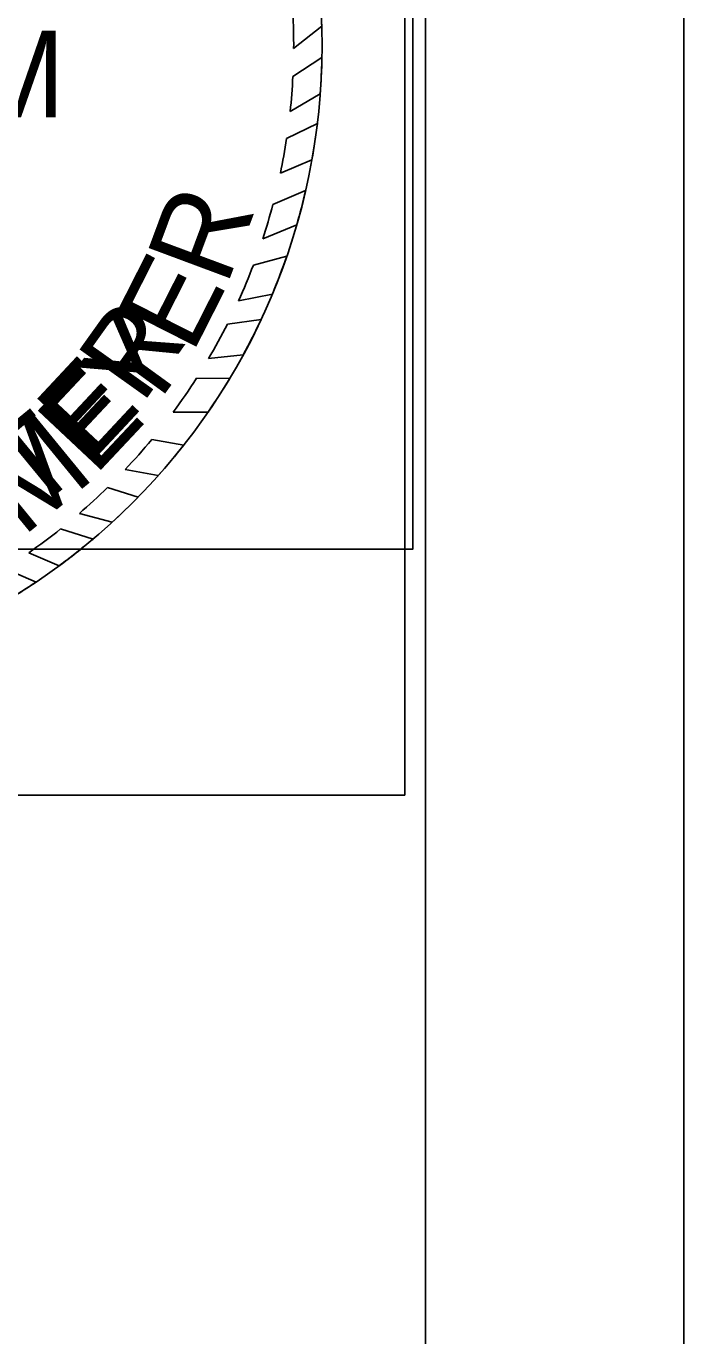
# Model space of a CAD drawing. Extents: x -0.29 to 1.42, y 0 to 0.92.
# Drawn here: x 1.3636 to 1.4167, y 0.689 to 0.7945 of the extents above; entities that cross this region are included whole.
import ezdxf

# ---------------------------------------------------------------- set-up
doc = ezdxf.new("R2010")
doc.units = 0
for name, color, linetype in [('DSN_DRFT_Guideline-No-Plot', 7, 'Continuous'), ('SHET_Border-Lines', 7, 'Continuous'), ('SHET_Stamp-Seal', 7, 'Continuous'), ('STAMP_PE_BACKGROUND', 7, 'Continuous'), ('STAMP_PE_FOSTER', 7, 'Continuous'), ('STAMP_PE_SEAL-INFO', 7, 'Continuous'), ('STAMP_PE_TAEGTMEYER', 7, 'Continuous'), ('STAMP_PRELIMINARY', 7, 'Continuous')]:
    doc.layers.add(name, color=color, linetype=linetype)

msp = doc.modelspace()

# ---------------------------------------------------------------- linework, layer by layer
at = {"layer": 'DSN_DRFT_Guideline-No-Plot'}
msp.add_lwpolyline([(0, 0), (1.416666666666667, 0), (1.416666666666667, 0.9166666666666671), (0, 0.9166666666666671)], close=True, dxfattribs=at)
at = {"layer": 'SHET_Border-Lines'}
msp.add_lwpolyline([(0.02083333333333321, 0.02083333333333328), (1.3958333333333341, 0.02083333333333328), (1.3958333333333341, 0.8958333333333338), (0.02083333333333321, 0.8958333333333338)], close=True, dxfattribs=at)
at = {"layer": 'SHET_Stamp-Seal'}
msp.add_lwpolyline([(1.2948333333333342, 0.7523810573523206), (1.3948333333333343, 0.7523810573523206), (1.3948333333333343, 0.8523810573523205), (1.2948333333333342, 0.8523810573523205)], close=True, dxfattribs=at)
at = {"layer": 'STAMP_PE_BACKGROUND'}
msp.add_lwpolyline([(1.3941666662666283, 0.8517143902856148), (1.2749999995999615, 0.8517143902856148), (1.2749999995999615, 0.7325477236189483), (1.3941666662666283, 0.7325477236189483)], close=True, dxfattribs=at)
msp.add_lwpolyline([(1.3941666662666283, 0.8517143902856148), (1.2749999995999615, 0.8517143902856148), (1.2749999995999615, 0.7325477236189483), (1.3941666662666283, 0.7325477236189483)], close=True, dxfattribs=at)
at = {"layer": 'STAMP_PE_SEAL-INFO'}
for p, q in [((1.3852134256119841, 0.7927322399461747), (1.3874764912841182, 0.7945290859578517)), ((1.3852134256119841, 0.7927322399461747), (1.3874764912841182, 0.7945290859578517)), ((1.3851513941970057, 0.7904687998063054), (1.3874913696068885, 0.7920162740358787)), ((1.3851513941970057, 0.7904687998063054), (1.3874913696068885, 0.7920162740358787)), ((1.3849286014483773, 0.7876409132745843), (1.3873544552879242, 0.7890734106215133)), ((1.3849286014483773, 0.7876409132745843), (1.3873544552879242, 0.7890734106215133)), ((1.3846467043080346, 0.78546942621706), (1.3871215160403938, 0.7866968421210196)), ((1.3846467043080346, 0.78546942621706), (1.3871215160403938, 0.7866968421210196)), ((1.3841397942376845, 0.7826771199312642), (1.3866817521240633, 0.7837684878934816)), ((1.3841397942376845, 0.7826771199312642), (1.3866817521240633, 0.7837684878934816)), ((1.383537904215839, 0.7801535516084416), (1.38617225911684, 0.7812792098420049)), ((1.383537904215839, 0.7801535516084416), (1.38617225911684, 0.7812792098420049)), ((1.382716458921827, 0.7773919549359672), (1.3854553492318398, 0.7785143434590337)), ((1.382716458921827, 0.7773919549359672), (1.3854553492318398, 0.7785143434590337)), ((1.3819640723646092, 0.7752694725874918), (1.3846604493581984, 0.7760019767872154)), ((1.3819640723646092, 0.7752694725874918), (1.3846604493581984, 0.7760019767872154)), ((1.380767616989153, 0.772395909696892), (1.383494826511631, 0.7729353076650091)), ((1.380767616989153, 0.772395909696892), (1.383494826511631, 0.7729353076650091)), ((1.3798679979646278, 0.7705177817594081), (1.3825944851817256, 0.7708979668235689)), ((1.3798679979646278, 0.7705177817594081), (1.3825944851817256, 0.7708979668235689)), ((1.378347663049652, 0.7677314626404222), (1.3811465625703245, 0.7680354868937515)), ((1.378347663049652, 0.7677314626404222), (1.3811465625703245, 0.7680354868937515)), ((1.377387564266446, 0.7661648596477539), (1.3800548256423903, 0.7661295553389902)), ((1.377387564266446, 0.7661648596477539), (1.3800548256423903, 0.7661295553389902)), ((1.3754905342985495, 0.7634033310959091), (1.3783092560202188, 0.7634195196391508)), ((1.3754905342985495, 0.7634033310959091), (1.3783092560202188, 0.7634195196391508)), ((1.3737701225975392, 0.7612030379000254), (1.376349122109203, 0.7607586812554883)), ((1.3737701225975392, 0.7612030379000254), (1.376349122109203, 0.7607586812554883)), ((1.3716298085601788, 0.7587828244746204), (1.374294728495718, 0.7583064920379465)), ((1.3716298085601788, 0.7587828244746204), (1.374294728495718, 0.7583064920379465)), ((1.3702058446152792, 0.7573345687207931), (1.3726690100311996, 0.7565647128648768)), ((1.3702058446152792, 0.7573345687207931), (1.3726690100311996, 0.7565647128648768)), ((1.367938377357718, 0.7552535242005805), (1.3705713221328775, 0.7545349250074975)), ((1.367938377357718, 0.7552535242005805), (1.3705713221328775, 0.7545349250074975)), ((1.3664259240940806, 0.7540003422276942), (1.3690398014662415, 0.7531880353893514)), ((1.3664259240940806, 0.7540003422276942), (1.3690398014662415, 0.7531880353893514)), ((1.3638530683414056, 0.7520847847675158), (1.3663034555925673, 0.7510277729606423)), ((1.3638530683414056, 0.7520847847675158), (1.3663034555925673, 0.7510277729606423)), ((1.3619321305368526, 0.7508134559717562), (1.364443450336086, 0.7497195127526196)), ((1.3619321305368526, 0.7508134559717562), (1.364443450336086, 0.7497195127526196))]:
    msp.add_line(p, q, dxfattribs=at)
for radius, start, end in [(0.05208333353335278, 1.7215475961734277, 4.7268136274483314), (0.05208333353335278, 1.7215475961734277, 4.7268136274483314), (0.04979730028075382, 359.7328912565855, 3.0639197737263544), (0.04979730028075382, 359.7328912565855, 3.0639197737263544), (0.05208333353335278, 355.71562332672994, 358.956939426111), (0.05208333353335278, 355.71562332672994, 358.956939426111), (0.04979730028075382, 353.86318650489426, 357.12741991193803), (0.04979730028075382, 353.86318650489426, 357.12741991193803), (0.05208333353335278, 349.83046937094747, 353.08845194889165), (0.05208333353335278, 349.83046937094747, 353.08845194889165), (0.04979730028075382, 348.07782395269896, 351.34354893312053), (0.04979730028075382, 348.07782395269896, 351.34354893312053), (0.05208333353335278, 343.8924710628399, 347.03501976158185), (0.05208333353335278, 343.8924710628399, 347.03501976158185), (0.04979730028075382, 341.7769864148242, 345.0924752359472), (0.04979730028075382, 341.7769864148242, 345.0924752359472), (0.05208333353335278, 337.3836727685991, 340.99332282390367), (0.05208333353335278, 337.3836727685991, 340.99332282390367), (0.04979730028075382, 335.60379596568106, 339.1857838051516), (0.04979730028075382, 335.60379596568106, 339.1857838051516), (0.05208333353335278, 331.4037138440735, 334.933154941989), (0.05208333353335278, 331.4037138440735, 334.933154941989), (0.04979730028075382, 329.55488416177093, 333.20757358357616), (0.04979730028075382, 329.55488416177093, 333.20757358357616), (0.04979730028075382, 323.58513069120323, 327.44068976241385), (0.04979730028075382, 323.58513069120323, 327.44068976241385), (0.05208333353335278, 325.4405170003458, 328.9872482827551), (0.05208333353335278, 325.4405170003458, 328.9872482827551), (0.04979730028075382, 316.6530849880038, 320.3710862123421), (0.04979730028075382, 316.6530849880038, 320.3710862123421), (0.05208333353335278, 318.2845512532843, 321.8042854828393), (0.05208333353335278, 318.2845512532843, 321.8042854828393), (0.04979730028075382, 310.7743619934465, 314.31605044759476), (0.04979730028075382, 310.7743619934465, 314.31605044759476), (0.05208333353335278, 312.45177291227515, 315.66328088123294), (0.05208333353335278, 312.45177291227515, 315.66328088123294), (0.04979730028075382, 304.8229923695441, 308.51427595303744), (0.04979730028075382, 304.8229923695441, 308.51427595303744), (0.05208333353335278, 306.37206251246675, 310.20798964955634), (0.05208333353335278, 306.37206251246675, 310.20798964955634), (0.05208333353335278, 300.6210136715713, 303.87026284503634), (0.05208333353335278, 300.6210136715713, 303.87026284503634)]:
    msp.add_arc((1.3354166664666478, 0.7929643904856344), radius, start, end, dxfattribs=at)
at = {"layer": 'STAMP_PRELIMINARY'}
msp.add_circle((1.3354166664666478, 0.7929643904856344), 0.05208333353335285, dxfattribs=at)
msp.add_circle((1.3354166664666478, 0.7929643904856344), 0.05208333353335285, dxfattribs=at)

# ---------------------------------------------------------------- texts
at = {"layer": 'STAMP_PE_FOSTER'}
for s, height, rotation, p in [('R', 0.006704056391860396, 54.50309997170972, (1.372983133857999, 0.763975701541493)), ('R', 0.006704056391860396, 54.50309997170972, (1.372983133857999, 0.763975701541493)), ('E', 0.006704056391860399, 46.96130660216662, (1.3689405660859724, 0.7593892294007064)), ('E', 0.006704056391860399, 46.96130660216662, (1.3689405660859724, 0.7593892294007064)), ('T', 0.006704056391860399, 39.41937898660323, (1.3641451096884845, 0.7551985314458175)), ('T', 0.006704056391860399, 39.41937898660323, (1.3641451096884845, 0.7551985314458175))]:
    msp.add_text(s, height=height, rotation=rotation, dxfattribs=at).set_placement(p)
at = {"layer": 'STAMP_PE_TAEGTMEYER'}
for s, height, rotation, p in [('R', 0.006983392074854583, 69.57000985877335, (1.379803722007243, 0.7734919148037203)), ('R', 0.006983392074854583, 69.57000985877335, (1.379803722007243, 0.7734919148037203)), ('E', 0.00698339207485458, 63.09839547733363, (1.3770182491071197, 0.7680080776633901)), ('E', 0.00698339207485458, 63.09839547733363, (1.3770182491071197, 0.7680080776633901)), ('Y', 0.006983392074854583, 53.99864225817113, (1.3732806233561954, 0.7627534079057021)), ('Y', 0.006983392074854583, 53.99864225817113, (1.3732806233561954, 0.7627534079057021)), ('E', 0.006983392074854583, 46.80937910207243, (1.3691516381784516, 0.758199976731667)), ('E', 0.006983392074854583, 46.80937910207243, (1.3691516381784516, 0.758199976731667)), ('M', 0.00698339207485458, 39.30004668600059, (1.3633390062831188, 0.7532885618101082)), ('M', 0.00698339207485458, 39.30004668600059, (1.3633390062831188, 0.7532885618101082))]:
    msp.add_text(s, height=height, rotation=rotation, dxfattribs=at).set_placement(p)
at = {"layer": 'STAMP_PRELIMINARY'}
msp.add_text('PICKERING FIRM', height=0.006983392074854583, dxfattribs=at).set_placement((1.2900146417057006, 0.7871721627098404))
msp.add_text('PICKERING FIRM', height=0.006983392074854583, dxfattribs=at).set_placement((1.2900146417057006, 0.7871721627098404))

doc.saveas('drawing.dxf')
